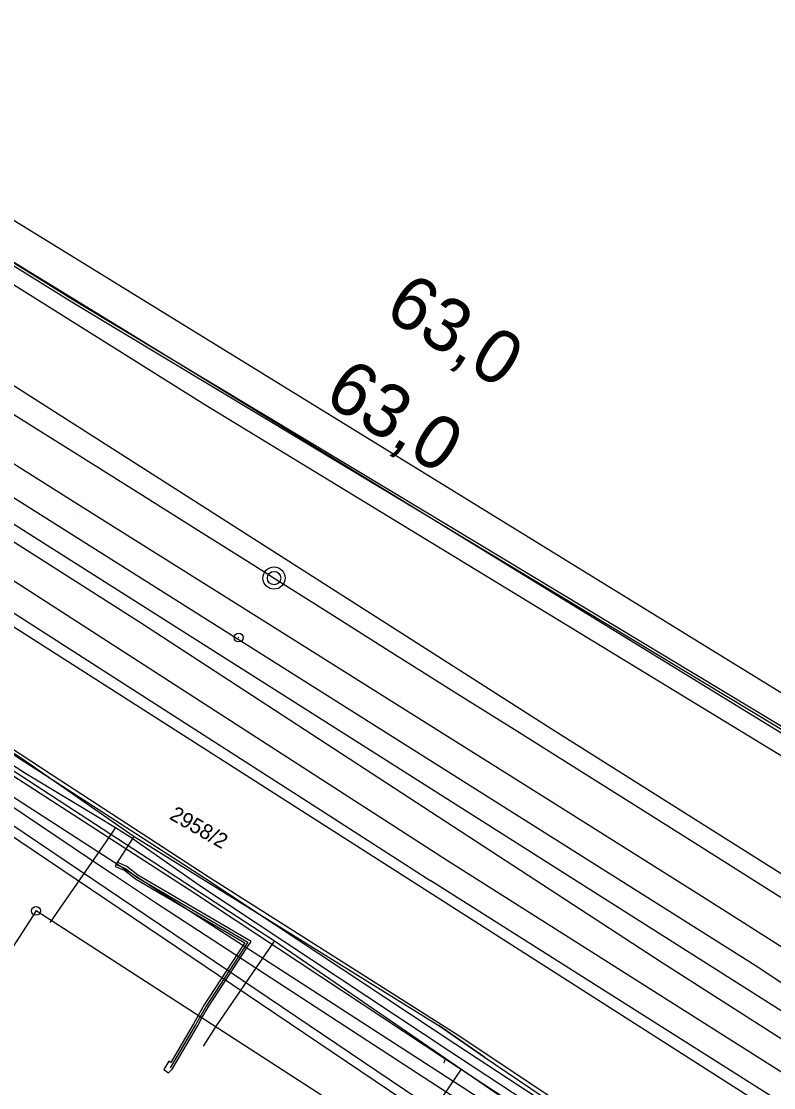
# Model space of a CAD drawing. Extents: x -621168 to -620292, y -1122748 to -1122069.
# Drawn here: x -620659.1 to -620574.7, y -1122523.2 to -1122403.6 of the extents above; entities that cross this region are included whole.
import ezdxf

# ---------------------------------------------------------------- set-up
doc = ezdxf.new("R2010")
doc.units = 0
for name, color, linetype in [('060601_EOV', 7, 'Continuous'), ('060604_ROZVODY_SEE', 7, 'Continuous'), ('CETIN', 7, 'Continuous'), ('GasNet', 7, 'Continuous'), ('HranDP', 7, 'Continuous'), ('Hranice parcel', 7, 'Continuous'), ('itself', 7, 'Continuous'), ('Parcelní čísla', 7, 'Continuous'), ('PS 06-14-01_trasa_sdělovací_nové', 7, 'Continuous'), ('SEE', 7, 'Continuous'), ('SSZT', 7, 'Continuous'), ('SSZT-DK', 7, 'Continuous'), ('VAS stoka', 7, 'Continuous'), ('VAS vodovod', 7, 'Continuous'), ('Vnitřní kresba', 7, 'Continuous'), ('Vrstva 1', 7, 'Continuous'), ('Vrstva 62', 7, 'Continuous'), ('Vrstva 7', 7, 'Continuous'), ('Věcná břemena k části', 7, 'Continuous'), ('Značky bodu BP', 7, 'Continuous'), ('ČD-T', 7, 'Continuous')]:
    doc.layers.add(name, color=color, linetype=linetype)

msp = doc.modelspace()

# ---------------------------------------------------------------- linework, layer by layer
at = {"layer": '060601_EOV'}
msp.add_lwpolyline([(-620377.18, -1122637.26), (-620411.56, -1122614.92), (-620424.16, -1122607.09), (-620443.53, -1122595), (-620456.11, -1122587.12), (-620447.82, -1122572.96), (-620450.95, -1122571.45), (-620470.59, -1122561.48), (-620499.61, -1122545.57), (-620522.04, -1122531.47), (-620538.89, -1122521.21), (-620599.21, -1122483.22), (-620683.52, -1122429.44), (-620729.12, -1122400.66), (-620738.89, -1122415.69), (-620750.53, -1122408.25), (-620763.56, -1122399.82), (-620784.65, -1122386.39), (-620822.22, -1122362.42), (-620817.53, -1122355.08), (-620826.41, -1122348.08), (-620839.92, -1122337.94), (-620848.84, -1122332), (-620848.83, -1122331.99)], dxfattribs=at)
at = {"layer": '060604_ROZVODY_SEE'}
msp.add_lwpolyline([(-620443.53, -1122595), (-620456.11, -1122587.12), (-620447.82, -1122572.96), (-620450.95, -1122571.45), (-620470.59, -1122561.48), (-620499.61, -1122545.57), (-620522.04, -1122531.47), (-620538.89, -1122521.21), (-620599.21, -1122483.22), (-620683.52, -1122429.44), (-620729.12, -1122400.66), (-620738.89, -1122415.69), (-620750.53, -1122408.25), (-620763.56, -1122399.82), (-620784.65, -1122386.39), (-620822.22, -1122362.42), (-620817.53, -1122355.08), (-620826.41, -1122348.08), (-620839.92, -1122337.94), (-620854.57, -1122328.18), (-620868.06, -1122319.69), (-620885.37, -1122308.82), (-620912.87, -1122291.53), (-620913.33, -1122292.25)], dxfattribs=at)
at = {"layer": 'CETIN'}
for points in [[(-621086.89, -1122186.72), (-621044.7, -1122204.84), (-620975.94, -1122239.69), (-620943.1, -1122258.62), (-620748.44, -1122376.27), (-620484.52, -1122538.15)], [(-620685.49, -1122468.76), (-620683.38, -1122470.13), (-620676.74, -1122474.66), (-620659.07, -1122486.24), (-620646.43, -1122495.05)], [(-620648.44, -1122498.16), (-620646.43, -1122495.05)], [(-620648.44, -1122498.16), (-620646.43, -1122495.05)], [(-620646.43, -1122495.05), (-620612.92, -1122515.84), (-620612.23, -1122516.26), (-620607.1, -1122519.79), (-620583.87, -1122535.51), (-620565.48, -1122548.17), (-620561.56, -1122551.58), (-620557.36, -1122556.05), (-620552.9, -1122562.72), (-620546.13, -1122574.35), (-620544.03, -1122578.53)], [(-620648.44, -1122498.16), (-620647.38, -1122498.61), (-620646.14, -1122499.59)], [(-620648.44, -1122498.16), (-620647.38, -1122498.61), (-620646.14, -1122499.59), (-620633.65, -1122506.89), (-620638.34, -1122514.06), (-620639.54, -1122516.17), (-620642.38, -1122521.01)], [(-620646.14, -1122499.59), (-620633.65, -1122506.89)], [(-620633.65, -1122506.89), (-620638.34, -1122514.06)], [(-620638.34, -1122514.06), (-620639.54, -1122516.17), (-620642.38, -1122521.01)], [(-620607.1, -1122519.79), (-620612.23, -1122516.26)]]:
    msp.add_lwpolyline(points, dxfattribs=at)
at = {"layer": 'GasNet'}
for points in [[(-620782.63, -1122409.86), (-620782.01, -1122410.24), (-620780.25, -1122411.07), (-620777.02, -1122412.94), (-620768.84, -1122416.49), (-620765.93, -1122417.88), (-620758.63, -1122422.59), (-620737.62, -1122436.24), (-620727.26, -1122442.97), (-620706.73, -1122456.7), (-620700.22, -1122460.96), (-620682.51, -1122472.52), (-620658.5, -1122488), (-620649.67, -1122493.31), (-620649.45, -1122493.45), (-620648.52, -1122494.04), (-620647.09, -1122494.92), (-620646.9, -1122495.04), (-620639.06, -1122500.54), (-620610.88, -1122519.2), (-620586.31, -1122535.34), (-620573.22, -1122543.96)], [(-620648.52, -1122494.04), (-620649.59, -1122495.62), (-620655.51, -1122504.17)], [(-620655.51, -1122504.17), (-620655.67, -1122504.4), (-620655.88, -1122504.7)]]:
    msp.add_lwpolyline(points, dxfattribs=at)
at = {"layer": 'HranDP'}
for points in [[(-620847.72, -1122320.67), (-620838.83, -1122326.12), (-620768.63, -1122369.09), (-620748.53, -1122378.52), (-620702.13, -1122406.7), (-620691.02, -1122413.66), (-620638.48, -1122446.57), (-620552.09, -1122499.2)], [(-620821.12, -1122358.76), (-620741.46, -1122408.09), (-620679.51, -1122447.56), (-620545.92, -1122532.26), (-620521.41, -1122548.27), (-620511.29, -1122557.64)]]:
    msp.add_lwpolyline(points, dxfattribs=at)
at = {"layer": 'Hranice parcel'}
for p, q in [((-620688.16, -1122408.5), (-620548.9, -1122494.24)), ((-620660.74, -1122490.09), (-620576.58, -1122544.45))]:
    msp.add_line(p, q, dxfattribs=at)
for points in [[(-620847.72, -1122320.67), (-620838.83, -1122326.12), (-620768.63, -1122369.09), (-620748.53, -1122378.52), (-620702.13, -1122406.7), (-620691.02, -1122413.66), (-620638.48, -1122446.57), (-620552.09, -1122499.2)], [(-620821.12, -1122358.76), (-620741.46, -1122408.09), (-620679.51, -1122447.56), (-620545.92, -1122532.26), (-620521.41, -1122548.27), (-620511.29, -1122557.64)], [(-620821.12, -1122358.76), (-620807.67, -1122367.84), (-620645.72, -1122471.03), (-620587.17, -1122509.18), (-620511.29, -1122557.64)], [(-620557.45, -1122536.96), (-620684.91, -1122455.63), (-620825.92, -1122365.89)], [(-620581.67, -1122552.32), (-620657.43, -1122503.38), (-620713.46, -1122590.12)]]:
    msp.add_lwpolyline(points, dxfattribs=at)
at = {"layer": 'itself'}
msp.add_lwpolyline([(-620570.67, -1122549.95), (-620584.48, -1122540.56), (-620609.76, -1122524.78), (-620613.13, -1122522.62), (-620616.25, -1122520.59), (-620644.13, -1122502.42), (-620648.74, -1122499.33), (-620649.95, -1122498.54), (-620675.91, -1122481.07), (-620699.14, -1122464.9), (-620705.51, -1122460.51), (-620711.67, -1122456.57), (-620715.75, -1122454.11), (-620716.79, -1122453.45), (-620721.67, -1122450.84), (-620745.77, -1122435.49), (-620776.46, -1122415.3)], dxfattribs=at)
at = {"layer": 'PS 06-14-01_trasa_sdělovací_nové'}
msp.add_lwpolyline([(-620538.89, -1122521.21), (-620538.89, -1122521.21), (-620599.21, -1122483.22), (-620683.52, -1122429.44), (-620756.33, -1122383.52), (-620761.98, -1122392.4), (-620753.37, -1122398.54), (-620735.26, -1122410.11), (-620735.26, -1122410.11)], dxfattribs=at)
at = {"layer": 'SEE'}
msp.add_lwpolyline([(-620377.19, -1122637.27), (-620390.25, -1122629.02), (-620411.93, -1122614.96), (-620423.13, -1122608.01), (-620468.34, -1122579.91), (-620468.34, -1122579.91), (-620460.94, -1122568.1), (-620517.42, -1122533.03), (-620535, -1122522.48), (-620545.41, -1122539.45), (-620611.37, -1122497.7), (-620665.57, -1122462.75), (-620686.03, -1122449.83), (-620727.54, -1122423.18), (-620794.51, -1122379.86), (-620815.52, -1122356.95), (-620832.17, -1122344.66), (-620847.81, -1122332.59), (-620908.26, -1122294.69)], dxfattribs=at)
at = {"layer": 'SSZT'}
msp.add_lwpolyline([(-620879.24, -1122313.32), (-620842.99, -1122336.61), (-620835.05, -1122343.25), (-620812.66, -1122358.95), (-620764.9, -1122389.75), (-620688.59, -1122438.97), (-620596.98, -1122496.73), (-620576.74, -1122509.48), (-620506.75, -1122556.12), (-620447.29, -1122593.62), (-620377.76, -1122638.26)], dxfattribs=at)
at = {"layer": 'SSZT-DK'}
msp.add_lwpolyline([(-621084.33, -1122182.33), (-621080.25, -1122184.04), (-621051.5, -1122198.93), (-620999.37, -1122227), (-620959.93, -1122250.54), (-620931.35, -1122267.52), (-620900.27, -1122286.47), (-620889.15, -1122293.45), (-620783.74, -1122358.82), (-620712.75, -1122398.18), (-620653.12, -1122435.23), (-620617.36, -1122456.74), (-620574.42, -1122482.6), (-620528.16, -1122511.11), (-620496.31, -1122530.83), (-620515.02, -1122558.81), (-620500.38, -1122568.61), (-620465.39, -1122591.45), (-620452.16, -1122605.02), (-620438.23, -1122615.5), (-620392.31, -1122655.21), (-620389.25, -1122658.02)], dxfattribs=at)
at = {"layer": 'VAS stoka'}
msp.add_lwpolyline([(-620781.72, -1122408.87), (-620776.69, -1122412.14), (-620774.2, -1122412.02), (-620772.21, -1122412.95), (-620766.77, -1122415.95), (-620758.11, -1122421.89), (-620737.16, -1122435.39), (-620726.71, -1122442.22), (-620705.9, -1122455.54), (-620681.71, -1122471.08), (-620665.23, -1122481.83), (-620655.61, -1122488.12), (-620638.12, -1122499.53), (-620609.99, -1122517.38), (-620585.88, -1122533.44), (-620564.23, -1122548.6), (-620546.83, -1122572.05), (-620541.25, -1122582.33), (-620541.87, -1122584.42), (-620543.53, -1122584.85), (-620544.25, -1122585.03)], dxfattribs=at)
at = {"layer": 'VAS vodovod'}
msp.add_line((-620609.72, -1122521.13), (-620625.07, -1122543.73), dxfattribs=at)
for points in [[(-620783.05, -1122410.36), (-620779.49, -1122412.44), (-620776.82, -1122413.57), (-620766.15, -1122419), (-620759.23, -1122423.16), (-620738.05, -1122436.88), (-620666.7, -1122483.31), (-620630.69, -1122506.76), (-620611.44, -1122519.95), (-620587.32, -1122536.52), (-620566.14, -1122551.51), (-620558.22, -1122559.71), (-620551.85, -1122569.08), (-620547.83, -1122576.32), (-620546.15, -1122586.98), (-620546.1, -1122587.26)], [(-620630.69, -1122506.76), (-620630.78, -1122506.91), (-620634.04, -1122511.65), (-620637.29, -1122516.39), (-620638.69, -1122518.58)], [(-620611.68, -1122520.43), (-620611.56, -1122520.19), (-620611.44, -1122519.95)]]:
    msp.add_lwpolyline(points, dxfattribs=at)
at = {"layer": 'Vnitřní kresba'}
for p, q in [((-620810.36, -1122373.73), (-620648.08, -1122477.56)), ((-620648.08, -1122477.56), (-620625, -1122492.37)), ((-620625, -1122492.37), (-620613.12, -1122500)), ((-620570.69, -1122526.84), (-620613.12, -1122500))]:
    msp.add_line(p, q, dxfattribs=at)
at = {"layer": 'Vrstva 1'}
for points in [[(-620851.64, -1122327.08), (-620840.38, -1122334.59), (-620831.19, -1122341.26), (-620824.9, -1122346.12), (-620811.35, -1122356.78), (-620800.85, -1122364.55), (-620800.09, -1122365.07), (-620796.17, -1122367.69), (-620795.02, -1122368.44), (-620786.31, -1122373.93), (-620764.42, -1122387.67), (-620747.63, -1122398.19), (-620733.73, -1122406.89), (-620718.35, -1122416.52), (-620703.01, -1122426.15), (-620686.98, -1122436.2), (-620670.85, -1122446.34), (-620652.24, -1122458.03), (-620632.99, -1122470.12), (-620616.99, -1122480.17), (-620599.71, -1122491.04), (-620582.33, -1122501.97), (-620566.97, -1122511.73)], [(-620538.89, -1122521.21), (-620599.21, -1122483.22), (-620683.52, -1122429.44), (-620747.38, -1122389.13), (-620756.33, -1122383.52)], [(-620659.94, -1122447.67), (-620652.83, -1122452.14), (-620645.8, -1122456.55), (-620638.91, -1122460.88), (-620633.12, -1122464.53), (-620630.72, -1122466.04), (-620624.36, -1122470.05), (-620617.79, -1122474.19), (-620610.12, -1122479.01), (-620603.19, -1122483.36), (-620596.39, -1122487.64), (-620589.57, -1122491.93), (-620582.39, -1122496.45), (-620575.44, -1122500.82), (-620568.6, -1122505.12)], [(-620659.94, -1122447.67), (-620652.83, -1122452.14), (-620645.8, -1122456.55), (-620638.91, -1122460.88), (-620633.12, -1122464.53), (-620630.72, -1122466.04), (-620624.36, -1122470.05), (-620617.79, -1122474.19), (-620610.12, -1122479.01), (-620603.19, -1122483.36), (-620596.39, -1122487.64), (-620589.57, -1122491.93), (-620582.39, -1122496.45), (-620575.44, -1122500.82), (-620568.6, -1122505.12)]]:
    msp.add_lwpolyline(points, dxfattribs=at)
at = {"layer": 'Vrstva 62'}
for p, q in [((-620651.85, -1122457.42), (-620651.85, -1122457.42)), ((-620652.64, -1122458.63), (-620652.64, -1122458.63)), ((-620632.61, -1122469.5), (-620632.61, -1122469.5)), ((-620633.37, -1122470.75), (-620633.37, -1122470.75)), ((-620616.58, -1122479.56), (-620616.58, -1122479.56)), ((-620617.4, -1122480.77), (-620617.4, -1122480.77)), ((-620599.33, -1122490.43), (-620599.33, -1122490.43)), ((-620600.08, -1122491.66), (-620600.08, -1122491.66)), ((-620581.93, -1122501.35), (-620581.93, -1122501.35)), ((-620582.73, -1122502.59), (-620582.73, -1122502.59))]:
    msp.add_line(p, q, dxfattribs=at)
at = {"layer": 'Vrstva 7'}
msp.add_line((-620634.74, -1122472.68), (-620634.66, -1122472.73), dxfattribs=at)
msp.add_line((-620634.74, -1122472.68), (-620634.66, -1122472.73), dxfattribs=at)
for centre, radius in [((-620630.72, -1122466.04), 1.25), ((-620630.72, -1122466.04), 1.25), ((-620630.72, -1122466.04), 0.752), ((-620630.72, -1122466.04), 0.752), ((-620634.7, -1122472.71), 0.5), ((-620634.7, -1122472.71), 0.5)]:
    msp.add_circle(centre, radius, dxfattribs=at)
at = {"layer": 'Věcná břemena k části'}
for points in [[(-620572.64, -1122543.14), (-620585.76, -1122534.5), (-620610.33, -1122518.37), (-620638.51, -1122499.7), (-620681.97, -1122471.68), (-620706.18, -1122455.87), (-620726.71, -1122442.14), (-620758.09, -1122421.75), (-620765.44, -1122417.01)], [(-620766.42, -1122418.75), (-620759.17, -1122423.43), (-620727.81, -1122443.8), (-620707.28, -1122457.53), (-620683.05, -1122473.36), (-620639.61, -1122501.38), (-620611.43, -1122520.03), (-620586.86, -1122536.18), (-620573.8, -1122544.78)]]:
    msp.add_lwpolyline(points, dxfattribs=at)
for points in [[(-620662.49, -1122492.8), (-620663.99, -1122495.13), (-620660.86, -1122494.48), (-620566.61, -1122558.04), (-620561.72, -1122564.46), (-620556.24, -1122574.37), (-620550.21, -1122590.27), (-620556.49, -1122571.86), (-620560.88, -1122563.9), (-620565.91, -1122557.3), (-620661.78, -1122492.65)], [(-620648.54, -1122498.39), (-620647.51, -1122498.83), (-620646.28, -1122499.8), (-620640.29, -1122503.3), (-620634, -1122506.97), (-620634.18, -1122507.24), (-620638.55, -1122513.93), (-620639.24, -1122515.13), (-620638.82, -1122515.4), (-620638.13, -1122514.19), (-620633.76, -1122507.52), (-620633.3, -1122506.81), (-620646, -1122499.38), (-620647.25, -1122498.39), (-620648.34, -1122497.93), (-620648.4, -1122498.06)], [(-620638.82, -1122515.4), (-620639.24, -1122515.13), (-620639.76, -1122516.04), (-620642.31, -1122520.4), (-620642.54, -1122520.25), (-620643.08, -1122521.19), (-620642.55, -1122521.56), (-620642.16, -1122521.14), (-620639.32, -1122516.3)]]:
    msp.add_lwpolyline(points, close=True, dxfattribs=at)
at = {"layer": 'Značky bodu BP'}
for radius in [0.5, 0.0303]:
    msp.add_circle((-620657.43, -1122503.38), radius, dxfattribs=at)
at = {"layer": 'ČD-T'}
msp.add_lwpolyline([(-621084.19, -1122182.07), (-621080.06, -1122183.8), (-621051.32, -1122198.69), (-620999.18, -1122226.77), (-620959.75, -1122250.31), (-620931.16, -1122267.28), (-620900.08, -1122286.23), (-620888.96, -1122293.22), (-620783.56, -1122358.58), (-620712.56, -1122397.94), (-620652.93, -1122435), (-620617.18, -1122456.5), (-620574.24, -1122482.37), (-620527.97, -1122510.87), (-620481.08, -1122540.08), (-620497, -1122565.38), (-620499.27, -1122568.98), (-620465.21, -1122591.22), (-620451.97, -1122604.79), (-620438.05, -1122615.26), (-620392.12, -1122654.98), (-620389.1, -1122657.76)], dxfattribs=at)

# ---------------------------------------------------------------- texts
at = {"layer": 'Parcelní čísla'}
msp.add_text('2958/2', height=1.7, rotation=330, dxfattribs=at).set_placement((-620642.57, -1122493.01))
at = {"layer": 'Vrstva 7'}
for p in [(-620618.56, -1122436.57), (-620625.34, -1122446.18)]:
    msp.add_text('63,0', height=6, rotation=327.7935, dxfattribs=at).set_placement(p)

doc.saveas('drawing.dxf')
